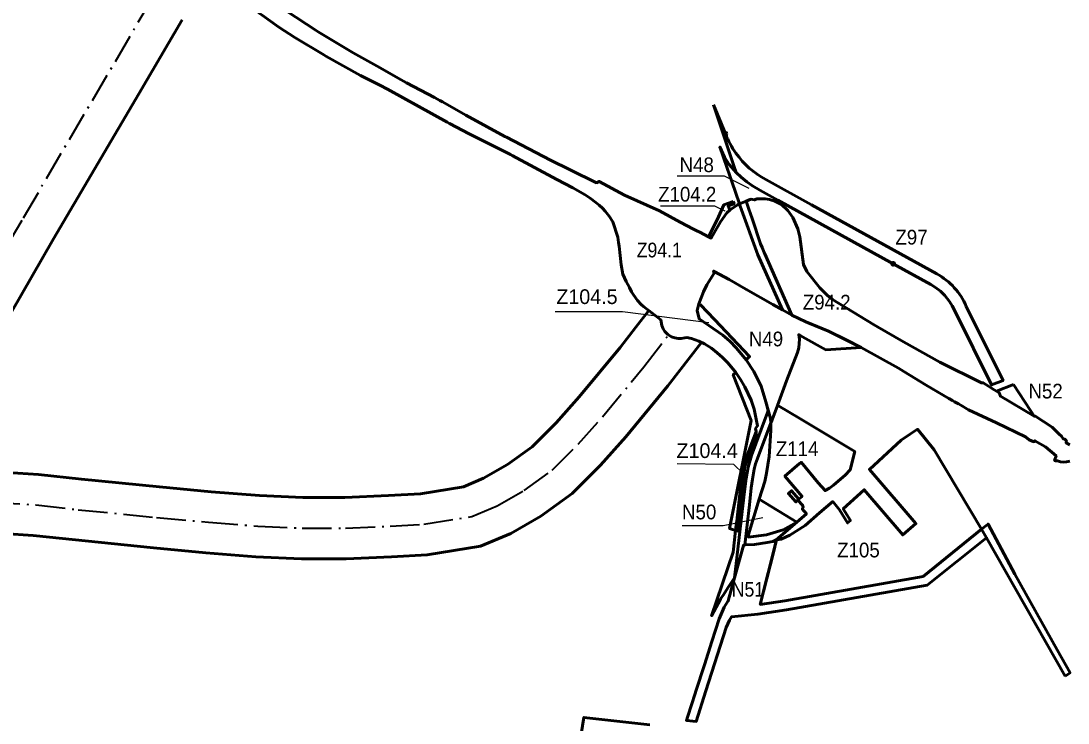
# Model space of a CAD drawing. Extents: x -650277 to -643422, y -1073980 to -1066720.
# Drawn here: x -647728 to -646020, y -1069362 to -1068218 of the extents above; entities that cross this region are included whole.
import ezdxf

# ---------------------------------------------------------------- set-up
doc = ezdxf.new("R2010")
doc.units = 0
doc.header["$LTSCALE"] = 9.6
doc.header["$PDMODE"] = 32
doc.header["$PDSIZE"] = 4.8
doc.linetypes.add('DOT_DASHED', pattern=[7.7, 5, -1.2, 0.3, -1.2])
for name, color, linetype, lineweight in [('13', 7, 'Continuous', 60), ('15', 7, 'Continuous', 60), ('24', 7, 'Continuous', 60), ('30', 7, 'Continuous', 60), ('34', 7, 'Continuous', 60), ('36', 7, 'Continuous', 60), ('42', 7, 'Continuous', 60), ('60', 7, 'Continuous', 60), ('61', 7, 'Continuous', 60), ('62', 7, 'DOT_DASHED', 40), ('63', 7, 'Continuous', 25), ('7', 7, 'Continuous', 60)]:
    doc.layers.add(name, color=color, linetype=linetype, lineweight=lineweight)

msp = doc.modelspace()

# ---------------------------------------------------------------- linework, layer by layer
at = {"layer": '13'}
msp.add_lwpolyline([(-646702.425, -1069364.771), (-646809.879, -1069353.002), (-646842.103, -1069553.182), (-646842.441, -1069555.283), (-646816.615, -1069558.064), (-646754.066, -1069567.993), (-646733.74, -1069471.688)], dxfattribs=at)
at = {"layer": '15'}
for points in [[(-646037.99, -1069242.88), (-646107, -1069119.41), (-646150.87, -1069037.64), (-646152.26, -1069038.76), (-646161.484, -1069046.228), (-646153.307, -1069059.947), (-646025.14, -1069285.394)], [(-646025.14, -1069285.394), (-646017.15, -1069280.19), (-646037.99, -1069242.88)]]:
    msp.add_lwpolyline(points, dxfattribs=at)
at = {"layer": '24'}
for points in [[(-646562.49, -1068790.69), (-646566.34, -1068794.32), (-646537.3, -1068868.95), (-646572.42, -1069044.94), (-646562.61, -1069048.08)], [(-646526.64, -1068877.47), (-646532.16, -1068850.47), (-646537.35, -1068835.56), (-646547.68, -1068814.22), (-646554.8, -1068801.98), (-646562.49, -1068790.69)], [(-646562.61, -1069048.08), (-646561.134, -1069035.627), (-646560.79, -1069032.72), (-646560.2, -1069027.69), (-646555.62, -1068988.63), (-646555, -1068983.32), (-646550.3, -1068943.27), (-646537.69, -1068909.82), (-646528.92, -1068886.55)], [(-646528.92, -1068886.55), (-646530.06, -1068882.16), (-646526.64, -1068877.47)], [(-646555.84, -1069050.22), (-646550.89, -1069007.7), (-646549.81, -1068998.88), (-646549.17, -1068993.71), (-646545.42, -1068963.3), (-646542.16, -1068945.12), (-646536.54, -1068925.95), (-646533.28, -1068917.17), (-646529.44, -1068906.81), (-646529.146, -1068895.373), (-646529.36, -1068895.94), (-646535.79, -1068912.99), (-646547.46, -1068943.97), (-646552.58, -1068987.63), (-646553.2, -1068992.9), (-646556.02, -1069016.97), (-646557.96, -1069033.47), (-646558.145, -1069035.029)], [(-646558.145, -1069035.029), (-646559.8, -1069048.98), (-646555.84, -1069050.22)]]:
    msp.add_lwpolyline(points, dxfattribs=at)
at = {"layer": '30'}
msp.add_line((-646583.49, -1068729.76), (-646571.91, -1068739.54), dxfattribs=at)
for points in [[(-646566.33, -1068512.04), (-646581.64, -1068517.24), (-646590.31, -1068536.69), (-646602.01, -1068560.15), (-646606.59, -1068569.33)], [(-646587.28, -1068545.28), (-646577.07, -1068530.2), (-646572.02, -1068526.07), (-646574.48, -1068518.75), (-646565.04, -1068515.86), (-646566.33, -1068512.04)], [(-646599.75, -1068566.49), (-646587.28, -1068545.28), (-646587.28, -1068545.28)], [(-646606.59, -1068569.33), (-646602.21, -1068571.5), (-646599.75, -1068566.49)], [(-646571.91, -1068739.54), (-646561.5, -1068750.22), (-646545.32, -1068769.89), (-646539.78, -1068764.65), (-646596.93, -1068704.15), (-646619.74, -1068680.15), (-646622.68, -1068678.75), (-646625.35, -1068689.7)], [(-646625.35, -1068689.7), (-646622.01, -1068703.3), (-646583.49, -1068729.76)]]:
    msp.add_lwpolyline(points, dxfattribs=at)
at = {"layer": '34'}
msp.add_lwpolyline([(-646161.484, -1069046.228), (-646238.632, -1068916.799), (-646266.118, -1068883.048), (-646277.268, -1068890.446), (-646292.75, -1068900.72), (-646344.49, -1068948.736), (-646268.528, -1069036.82), (-646290.099, -1069055.423), (-646352.71, -1068981.82), (-646386.936, -1069012.936), (-646375.346, -1069032.07), (-646379.973, -1069035.889), (-646393.09, -1069014.234), (-646404.269, -1069001.033), (-646425.52, -1069019.41), (-646449.418, -1069039.804), (-646474.13, -1069055.83), (-646488.537, -1069062.169), (-646495.89, -1069063.531), (-646500.995, -1069083.812), (-646522.35, -1069168.648), (-646482.211, -1069162.813), (-646256.824, -1069123.414)], close=True, dxfattribs=at)
at = {"layer": '36'}
msp.add_lwpolyline([(-646512.07, -1068954.68), (-646507.91, -1068927.47), (-646505.12, -1068885.31), (-646505.17, -1068872.78), (-646503.24, -1068867.61), (-646494.52, -1068844.29), (-646492.73, -1068845.01), (-646457.86, -1068865.8), (-646430.86, -1068881.89), (-646368.3, -1068919.19), (-646376.02, -1068949.34), (-646383.86, -1068958.24), (-646403.13, -1068974.41), (-646409.67, -1068979.3), (-646416.71, -1068983.21), (-646427.77, -1068970.39), (-646455.78, -1068936.87), (-646458.21, -1068938.99), (-646482.2, -1068959.52), (-646454.21, -1068992.73), (-646459.25, -1068996.98), (-646471.24, -1068983.41), (-646476.35, -1068987.98), (-646464.24, -1069001.49), (-646461.29, -1068998.81), (-646453.48, -1069006.75), (-646452.37, -1069010.01), (-646453.88, -1069013.1), (-646447.2, -1069020.9), (-646462.98, -1069034.61), (-646524, -1068997), (-646514.91, -1068968.48), (-646514.91, -1068968.48)], close=True, dxfattribs=at)
at = {"layer": '42'}
for points in [[(-646561.544, -1068464.842), (-646572.984, -1068451.81), (-646580.625, -1068439.803), (-646588.07, -1068422.96), (-646576.4, -1068457.27), (-646568.87, -1068479.14), (-646556.22, -1068515.84), (-646545.57, -1068511.42), (-646537.71, -1068508.16)], [(-646523.105, -1068493.54), (-646535.245, -1068486.342), (-646544.525, -1068479.79), (-646553.677, -1068472.283), (-646561.544, -1068464.842)], [(-646537.71, -1068508.16), (-646531.9, -1068509.25), (-646528.18, -1068507.58), (-646514.39, -1068507.56), (-646507.4, -1068508.45), (-646498.48, -1068511.26), (-646495.416, -1068512.888), (-646493.511, -1068509.855), (-646523.105, -1068493.54)], [(-646075.56, -1068861.95), (-646130.68, -1068829.21), (-646132.62, -1068823.54), (-646136.99, -1068820.88), (-646109.35, -1068810.23)], [(-646109.35, -1068810.23), (-646081.72, -1068852.51), (-646075.56, -1068861.95)]]:
    msp.add_lwpolyline(points, dxfattribs=at)
for points in [[(-646609.7, -1068647.84), (-646615.19, -1068659.11), (-646622.68, -1068678.75), (-646619.74, -1068680.15), (-646596.93, -1068704.15), (-646539.78, -1068764.65), (-646545.32, -1068769.89), (-646532.92, -1068788.95), (-646521.18, -1068812.95), (-646513.27, -1068838.37), (-646505.69, -1068865.56), (-646505.17, -1068872.78), (-646503.24, -1068867.61), (-646494.52, -1068844.29), (-646479.45, -1068804.37), (-646461.92, -1068757.93), (-646459.59, -1068750.19), (-646458.57, -1068736.31), (-646459.54, -1068728.94), (-646453.51, -1068732.3), (-646415.3, -1068753.62), (-646357.87, -1068749.64), (-646411.3, -1068723.11), (-646448.02, -1068707.99), (-646470.65, -1068697.38), (-646486.23, -1068688.54), (-646501.64, -1068679.81), (-646545.73, -1068654.81), (-646573.14, -1068638.98), (-646598.59, -1068625.34), (-646597.4, -1068628.74)], [(-646541.71, -1069054.76), (-646542, -1069059), (-646512, -1069055), (-646485, -1069047), (-646462.98, -1069034.61), (-646524, -1068997)]]:
    msp.add_lwpolyline(points, close=True, dxfattribs=at)
at = {"layer": '60'}
msp.add_line((-646578.881, -1068401.54), (-646598.635, -1068354.436), dxfattribs=at)
for points in [[(-647419.713, -1068138.871), (-647405.71, -1068151.74), (-647372.38, -1068179.01), (-647337.74, -1068205.67), (-647334.62, -1068208.02), (-647307.39, -1068227.44), (-647281.64, -1068244.34), (-647234.11, -1068273.04), (-647230.83, -1068274.93), (-647174.56, -1068306.35), (-647142.788, -1068322.462), (-647130.29, -1068328.8), (-647079.16, -1068357.01), (-647032.91, -1068382.51), (-647029.23, -1068384.46), (-646997.06, -1068401.37), (-646929.56, -1068435.42), (-646927.06, -1068436.66)], [(-646634.37, -1068735.27), (-646622.62, -1068739.32), (-646613.44, -1068743.65), (-646601.86, -1068751.01), (-646592.53, -1068758.66), (-646583.98, -1068766.42), (-646575.28, -1068775.04), (-646562.49, -1068790.69), (-646554.8, -1068801.98), (-646547.68, -1068814.22), (-646537.35, -1068835.56), (-646532.16, -1068850.47), (-646526.64, -1068877.47), (-646530.06, -1068882.16), (-646528.92, -1068886.55), (-646529.44, -1068906.81), (-646510.56, -1068855.86), (-646509.323, -1068852.529), (-646513.27, -1068838.37), (-646521.18, -1068812.95), (-646532.92, -1068788.95), (-646545.32, -1068769.89), (-646561.5, -1068750.22), (-646571.91, -1068739.54), (-646583.49, -1068729.76), (-646622.01, -1068703.3), (-646625.35, -1068689.7), (-646622.68, -1068678.75), (-646615.19, -1068659.11), (-646609.7, -1068647.84), (-646597.4, -1068628.74), (-646596.28, -1068626.52), (-646596.28, -1068626.52), (-646573.14, -1068638.98), (-646545.73, -1068654.81), (-646545.73, -1068654.81), (-646501.64, -1068679.81), (-646486.23, -1068688.54), (-646526.1, -1068598.55), (-646555, -1068519.38), (-646555, -1068519.38), (-646556.22, -1068515.84), (-646559.72, -1068517.29), (-646569.61, -1068524.1), (-646572.02, -1068526.07), (-646577.07, -1068530.2), (-646587.28, -1068545.28), (-646599.75, -1068566.49), (-646602.21, -1068571.5), (-646606.59, -1068569.33), (-646620.94, -1068561.96), (-646625.86, -1068559.47), (-646631.18, -1068556.77), (-646653.21, -1068545.58), (-646686.84, -1068526.89), (-646686.84, -1068526.89), (-646743.69, -1068501.76), (-646785.05, -1068479.12), (-646787.55, -1068480.36), (-646789.49, -1068481.31), (-646832.29, -1068460.04), (-646864.48, -1068444.64), (-646936.47, -1068407.23), (-646938.95, -1068405.8), (-646967.64, -1068390), (-647002.71, -1068371.09), (-647040.77, -1068349.4), (-647044.93, -1068347.08), (-647053.75, -1068342.11), (-647099.2, -1068318.27), (-647112.813, -1068310.564), (-647142.41, -1068293.81), (-647186.26, -1068269.45), (-647243.39, -1068235.26), (-647246.8, -1068233.08), (-647295.47, -1068201.09)], [(-646598.635, -1068354.436), (-646579.62, -1068411.29), (-646564.78, -1068455.41), (-646561.544, -1068464.842)], [(-646927.06, -1068436.66), (-646854.18, -1068475.8), (-646828.2, -1068489.61), (-646807.82, -1068501.17), (-646799.79, -1068506.39), (-646790.66, -1068513.24), (-646785.34, -1068517.77), (-646779.93, -1068522.9), (-646775.44, -1068527.74), (-646768.95, -1068535.8), (-646763.1, -1068545.18), (-646754.92, -1068569.81), (-646753.35, -1068578.6), (-646752.59, -1068584.55), (-646749.35, -1068615.18), (-646746.32, -1068630.23), (-646740.91, -1068642.34), (-646735.62, -1068652.21), (-646732.25, -1068659.06), (-646729.34, -1068663.94), (-646722.6, -1068673.11), (-646716.39, -1068679.8), (-646716.39, -1068679.8), (-646712.93, -1068683), (-646684.7, -1068704.95), (-646682.98, -1068714.07), (-646680.88, -1068719.28), (-646678.08, -1068723.7), (-646673.16, -1068728.69), (-646667.17, -1068732.38), (-646667.17, -1068732.38), (-646661.5, -1068734.35), (-646656.47, -1068735.13), (-646651.21, -1068734.99), (-646645.18, -1068733.91), (-646642.04, -1068733.74), (-646634.37, -1068735.27)], [(-646561.544, -1068464.842), (-646553.677, -1068472.283), (-646544.525, -1068479.79), (-646535.245, -1068486.342), (-646523.105, -1068493.54), (-646493.511, -1068509.855), (-646305.678, -1068613.404)], [(-646234.342, -1068629.893), (-646234.342, -1068629.892), (-646438.626, -1068517.274), (-646513.45, -1068476.025), (-646513.567, -1068475.963)], [(-646337.93, -1068712.4), (-646404.83, -1068671.52), (-646413.45, -1068664.71), (-646422.32, -1068655.58), (-646425.11, -1068652.37), (-646446.54, -1068626.14), (-646451.82, -1068614.31), (-646458.03, -1068569.26), (-646461.14, -1068556.34), (-646469.51, -1068538.15), (-646477.41, -1068526.45), (-646487.92, -1068516.87), (-646498.48, -1068511.26), (-646507.4, -1068508.45), (-646514.39, -1068507.56), (-646528.18, -1068507.58), (-646531.9, -1068509.25), (-646537.71, -1068508.16), (-646545.57, -1068511.42), (-646541.06, -1068524.58), (-646535.84, -1068539.8), (-646521.81, -1068580.69), (-646519.14, -1068587.06), (-646516.07, -1068595.08), (-646515.09, -1068597.29), (-646470.65, -1068697.38), (-646448.02, -1068707.99), (-646444.51, -1068709.64), (-646411.3, -1068723.11), (-646380.94, -1068737.81), (-646357.87, -1068749.64), (-646297.08, -1068783.8), (-646288.37, -1068789.04), (-646251.73, -1068811.04), (-646214.92, -1068832.85), (-646208.7, -1068836.39), (-646205.48, -1068838.23), (-646199.24, -1068841.79), (-646195.52, -1068843.92), (-646182.57, -1068851.3)], [(-646305.678, -1068613.404), (-646243.997, -1068647.407), (-646236.707, -1068651.891), (-646228.691, -1068658.051), (-646221.348, -1068665.144), (-646213.659, -1068674.696), (-646209.179, -1068681.795), (-646204.654, -1068690.937), (-646145.083, -1068810.83), (-646126.317, -1068803.654), (-646186.371, -1068682.825)], [(-647756.441, -1069053.207), (-647708.401, -1069056.275), (-647511.94, -1069076.703), (-647426.417, -1069084.624), (-647344.902, -1069091.02), (-647270.522, -1069094.255), (-647197.498, -1069094.255), (-647123.648, -1069091.043), (-647065.688, -1069087.73), (-646978.92, -1069073.93), (-646929.186, -1069052.925), (-646880.163, -1069024.903), (-646829.104, -1068987.917), (-646782.784, -1068941.581), (-646741.85, -1068895.719), (-646673.05, -1068812.491), (-646618.655, -1068742.359), (-646617.991, -1068741.503), (-646622.62, -1068739.32), (-646634.37, -1068735.27), (-646642.04, -1068733.74), (-646645.18, -1068733.91), (-646651.21, -1068734.99), (-646656.47, -1068735.13), (-646661.5, -1068734.35), (-646667.17, -1068732.38), (-646673.16, -1068728.69), (-646678.08, -1068723.7), (-646680.88, -1068719.28), (-646682.98, -1068714.07), (-646684.7, -1068704.95), (-646704.316, -1068689.698), (-646725.374, -1068716.786), (-646751.116, -1068749.975), (-646817.718, -1068830.545), (-646855.506, -1068872.883), (-646894.206, -1068911.595), (-646934.465, -1068940.759), (-646973.61, -1068963.135), (-647006.63, -1068977.08), (-647076.422, -1068988.18), (-647128.674, -1068991.167), (-647199.672, -1068994.255), (-647268.348, -1068994.255), (-647338.816, -1068991.19), (-647417.895, -1068984.986), (-647502.412, -1068977.157), (-647629.424, -1068964.608), (-647699.561, -1068956.635), (-647749.978, -1068953.416)], [(-646017.39, -1068908.42), (-646023.56, -1068905.05), (-646023.13, -1068903.12), (-646023.92, -1068900.73), (-646025.57, -1068899.39), (-646028.18, -1068898.89), (-646031.31, -1068894.32), (-646034.65, -1068891.12), (-646046.48, -1068879.92), (-646074.78, -1068861.51), (-646075.56, -1068861.95), (-646130.68, -1068829.21), (-646132.62, -1068823.54), (-646136.99, -1068820.88), (-646140.73, -1068818.61), (-646146.85, -1068814.88), (-646150.26, -1068812.81), (-646159.1, -1068807.43), (-646161.45, -1068807.54), (-646229.44, -1068773.53), (-646288.59, -1068740.88), (-646331.26, -1068716.25), (-646337.93, -1068712.4)], [(-646182.57, -1068851.3), (-646137.23, -1068872.6), (-646089.63, -1068895.5), (-646084.1, -1068900.51), (-646076.09, -1068903.48), (-646074.51, -1068901.9), (-646057.13, -1068911.62), (-646039.84, -1068926.67), (-646042.5, -1068933.91), (-646040.65, -1068934.59), (-646037.5, -1068934.7), (-646032.61, -1068936.1), (-646027.69, -1068936.6), (-646022.77, -1068936.12), (-646017.6, -1068934.89)], [(-646505.17, -1068872.78), (-646526.81, -1068930.69), (-646530.08, -1068939.43), (-646532.13, -1068948), (-646535.13, -1068964.38), (-646537.02, -1068978.44), (-646539.77, -1069006.25)], [(-646524, -1068997), (-646514.91, -1068968.48), (-646514.91, -1068968.48), (-646512.07, -1068954.68), (-646507.91, -1068927.47), (-646505.12, -1068885.31), (-646505.17, -1068872.78)], [(-646539.77, -1069006.25), (-646539.77, -1069006.25), (-646547.412, -1069071.71)], [(-646462.98, -1069034.61), (-646485, -1069047), (-646512, -1069055), (-646542, -1069059), (-646541.71, -1069054.76), (-646524, -1068997)], [(-646547.412, -1069071.71), (-646532, -1069071), (-646511, -1069068), (-646502, -1069066), (-646496.317, -1069063.61), (-646462.98, -1069034.61)]]:
    msp.add_lwpolyline(points, dxfattribs=at)
msp.add_lwpolyline([(-646582.46, -1069152.81), (-646575.4, -1069141.46), (-646564.54, -1069125.08), (-646562.35, -1069106.21), (-646561.88, -1069102.18), (-646555.84, -1069050.22), (-646555.84, -1069050.22), (-646559.8, -1069048.98), (-646562.61, -1069048.08), (-646566.82, -1069083.62), (-646601.82, -1069187.25), (-646586.97, -1069160.06), (-646585.42, -1069157.56), (-646583.89, -1069155.1), (-646582.46, -1069152.81)], close=True, dxfattribs=at)
for centre, radius, start, end in [((-646447.332, -1068351.964), 140.58, 200.6496, 215.36619), ((-646447.332, -1068351.964), 140.58, 215.36631, 241.891), ((-646287.447, -1068726.224), 110, 23.23727, 61.13296)]:
    msp.add_arc(centre, radius, start, end, dxfattribs=at)
for p in [(-646578.881, -1068401.54), (-646305.678, -1068613.404)]:
    msp.add_point(p, dxfattribs=at)
at = {"layer": '61'}
msp.add_lwpolyline([(-647768.02, -1068570.36), (-647770.94, -1068622.47), (-647772.85, -1068656.41), (-647773.08, -1068660.57), (-647773.4, -1068665.71), (-647776.5, -1068714.8), (-647778.95, -1068752.433), (-647675.054, -1068572.919), (-647535.844, -1068336.279), (-647464.94, -1068215.752)], dxfattribs=at)
at = {"layer": '62'}
for points in [[(-647128.118, -1067439.088), (-647164.761, -1067539.408), (-647210.113, -1067645.071), (-647251.182, -1067728.502), (-647325.296, -1067860.04), (-647512.903, -1068178.95), (-647726.877, -1068542.68), (-647850.594, -1068756.441), (-647875.691, -1068807.609), (-647903.473, -1068876.174), (-647924.037, -1068940.973), (-647945.559, -1069039.601), (-647956.348, -1069145.994), (-647956.677, -1069214.977), (-647954.925, -1069248.93), (-647950.785, -1069292.731), (-647945.699, -1069329.377), (-647937.748, -1069374.683)], [(-647953.174, -1069007.503), (-647892.914, -1069003.305), (-647829.936, -1069000.155), (-647777.98, -1069001.73), (-647703.981, -1069006.455), (-647634.706, -1069014.33), (-647507.176, -1069026.93), (-647422.156, -1069034.805), (-647341.859, -1069041.105), (-647269.435, -1069044.255), (-647198.585, -1069044.255), (-647126.161, -1069041.105), (-647071.055, -1069037.955), (-646992.775, -1069025.505), (-646951.398, -1069008.03), (-646907.314, -1068982.831), (-646861.655, -1068949.756), (-646819.145, -1068907.232), (-646779.784, -1068863.132), (-646712.083, -1068781.233), (-646669.79, -1068726.705)]]:
    msp.add_lwpolyline(points, dxfattribs=at)
at = {"layer": '63'}
for points in [[(-646658, -1068470), (-646581, -1068470), (-646541, -1068490)], [(-646685, -1068519), (-646597, -1068519), (-646580, -1068527)], [(-646857, -1068691), (-646747, -1068691), (-646606, -1068709)], [(-646658, -1068939), (-646566, -1068940), (-646550, -1068955)], [(-646650, -1069040), (-646583, -1069040), (-646518, -1069027)]]:
    msp.add_lwpolyline(points, dxfattribs=at)
at = {"layer": '7'}
msp.add_lwpolyline([(-646522.35, -1069168.648), (-646495.89, -1069063.531), (-646496.317, -1069063.61), (-646496.317, -1069063.61), (-646502, -1069066), (-646511, -1069068), (-646532, -1069071), (-646547.412, -1069071.71), (-646549.91, -1069072.542), (-646564.54, -1069125.08), (-646564.605, -1069125.271), (-646574.978, -1069163.017), (-646574.978, -1069163.017), (-646574.33, -1069162.04), (-646575.87, -1069164.54), (-646581.29, -1069173.32), (-646589.56, -1069192.07), (-646601.41, -1069229.34), (-646613.6, -1069267.04), (-646627.59, -1069310.34), (-646628.66, -1069313.66), (-646640.715, -1069350.951), (-646642.89, -1069357.68), (-646626.774, -1069359.349), (-646611.107, -1069309.68), (-646577.878, -1069206.485), (-646572.586, -1069194.485), (-646569.114, -1069188.86), (-646526.31, -1069184.381), (-646479.84, -1069177.626), (-646250.409, -1069137.52), (-646153.307, -1069059.947), (-646161.484, -1069046.228), (-646256.824, -1069123.414), (-646482.211, -1069162.813)], close=True, dxfattribs=at)

# ---------------------------------------------------------------- texts
at = {"layer": '63'}
for s, width, p in [('N48', 0.95, (-646654, -1068464)), ('Z104.2', 0.95, (-646689, -1068512)), ('Z97', 0.95, (-646302, -1068582)), ('Z94.1', 0.9, (-646724, -1068603)), ('Z94.2', 0.95, (-646453, -1068688)), ('N49', 0.95, (-646541, -1068748)), ('N52', 0.95, (-646085, -1068833)), ('Z114', 0.95, (-646497, -1068927)), ('N50', 0.95, (-646650, -1069030)), ('Z105', 0.95, (-646397, -1069092)), ('N51', 0.9, (-646569, -1069156))]:
    msp.add_text(s, height=24, dxfattribs=dict(at, width=width)).set_placement(p)
for s, p in [('Z104.5', (-646855, -1068679)), ('Z104.4', (-646659, -1068930))]:
    msp.add_text(s, height=24, dxfattribs=at).set_placement(p)

doc.saveas('drawing.dxf')
